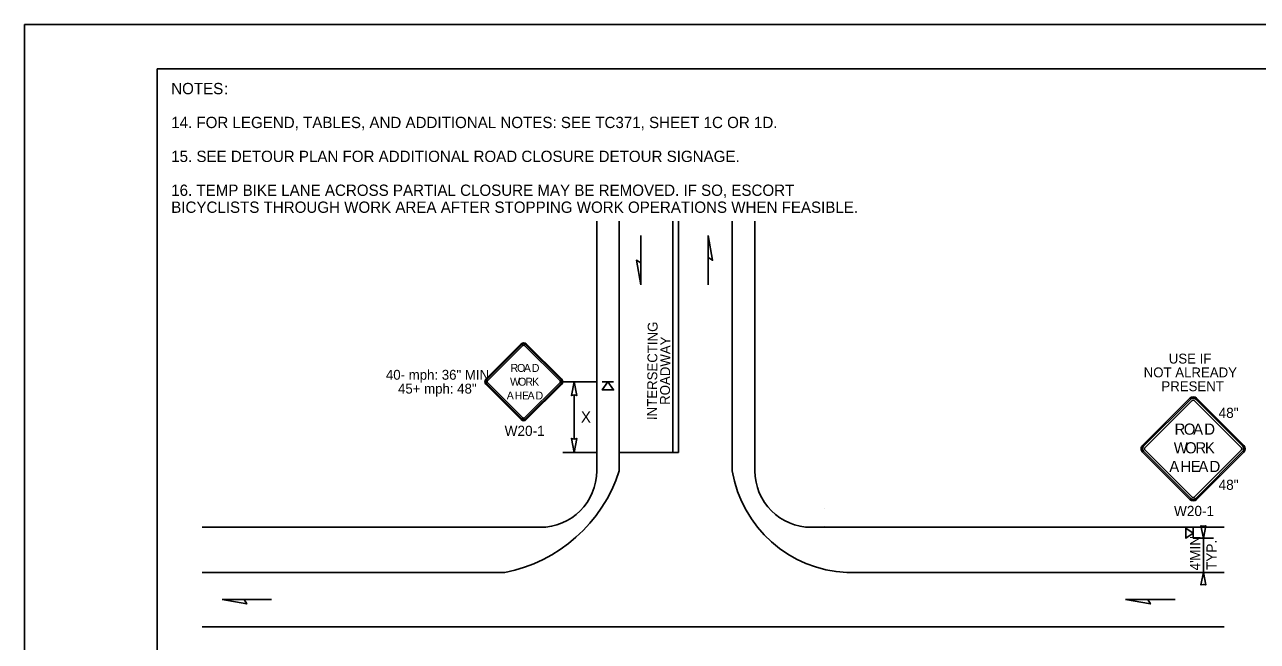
# Model space of a CAD drawing. Extents: x 99958 to 100136, y 99935 to 100013.
# Drawn here: x 100039.06 to 100047.79, y 99976.32 to 99980.69 of the extents above; entities that cross this region are included whole.
import ezdxf

# ---------------------------------------------------------------- set-up
doc = ezdxf.new("R2010")
doc.units = 0
for name, color, linetype in [('RD_ED_ShoulderPavedEdge', 7, 'Continuous'), ('RD_MK_LineDblYellowCenter', 7, 'Continuous'), ('RD_MK_LineEdgeWhite', 7, 'Continuous'), ('RD_MK_LineEdgeYellow', 7, 'Continuous'), ('RD_MK_LineLane', 7, 'Continuous'), ('RD_MK_LineStop', 7, 'Continuous'), ('SH_DE_DetailBody1Text', 7, 'Continuous'), ('SH_GI_GeneralNotesBodyText', 7, 'Continuous'), ('SH_GI_PlotLimits', 7, 'Continuous'), ('SH_GI_SheetBorder', 7, 'Continuous'), ('TR_SN_ConstructionSigns', 7, 'Continuous'), ('TR_WZ_PortableSignMountBlk-Org', 7, 'Continuous'), ('TR_WZ_WorkZoneDetails', 7, 'Continuous'), ('TR_WZ_WorkZoneTextCurrent', 7, 'Continuous')]:
    doc.layers.add(name, color=color, linetype=linetype)

msp = doc.modelspace()

# ---------------------------------------------------------------- linework, layer by layer
at = {"layer": 'RD_ED_ShoulderPavedEdge'}
for p, q in [((100040.32, 99977.1284), (100042.7119, 99977.1284)), ((100044.6319, 99977.1284), (100047.555, 99977.1284))]:
    msp.add_line(p, q, dxfattribs=at)
for points in [[(100043.1119, 99979.295), (100043.1119, 99977.5284)], [(100044.2319, 99979.295), (100044.2319, 99977.5284)]]:
    msp.add_lwpolyline(points, dxfattribs=at)
for centre, start, end in [((100042.7119, 99977.5284), 270, 0), ((100044.6319, 99977.5284), 180, 270)]:
    msp.add_arc(centre, 0.4, start, end, dxfattribs=at)
at = {"layer": 'RD_MK_LineDblYellowCenter'}
for p, q in [((100043.6519, 99979.295), (100043.6519, 99977.6584)), ((100043.6919, 99979.295), (100043.6919, 99977.6584))]:
    msp.add_line(p, q, dxfattribs=at)
at = {"layer": 'RD_MK_LineEdgeWhite'}
for p, q in [((100043.2719, 99977.5284), (100043.2719, 99979.295)), ((100044.0719, 99977.5284), (100044.0719, 99979.295))]:
    msp.add_line(p, q, dxfattribs=at)
for centre, radius, start, end in [((100042.257, 99977.8547), 1.0661, 281.08423, 342.18285), ((100044.9219, 99977.669), 0.8615, 189.3884, 267.34452)]:
    msp.add_arc(centre, radius, start, end, dxfattribs=at)
at = {"layer": 'RD_MK_LineEdgeYellow'}
for p, q in [((100040.32, 99976.8084), (100042.4619, 99976.8084)), ((100044.8819, 99976.8084), (100047.555, 99976.8084))]:
    msp.add_line(p, q, dxfattribs=at)
at = {"layer": 'RD_MK_LineLane'}
msp.add_lwpolyline([(100047.555, 99976.4244), (100040.32, 99976.4244)], dxfattribs=at)
at = {"layer": 'RD_MK_LineStop'}
msp.add_line((100043.6919, 99977.6584), (100043.2719, 99977.6584), dxfattribs=at)
at = {"layer": 'SH_GI_PlotLimits'}
msp.add_lwpolyline([(100039.0625, 99969.6875), (100056.0625, 99969.6875), (100056.0625, 99980.6875), (100039.0625, 99980.6875)], close=True, dxfattribs=at)
at = {"layer": 'SH_GI_SheetBorder'}
for q in [(100040, 99970), (100055.75, 99980.375)]:
    msp.add_line((100040, 99980.375), q, dxfattribs=at)
at = {"layer": 'TR_SN_ConstructionSigns'}
for p, q in [((100042.5782, 99978.4278), (100042.3276, 99978.1772)), ((100042.5831, 99978.4228), (100042.3325, 99978.1722)), ((100042.3395, 99978.1653), (100042.5901, 99978.4158)), ((100042.602, 99978.4158), (100042.8526, 99978.1653)), ((100042.8596, 99978.1722), (100042.609, 99978.4228)), ((100042.8645, 99978.1772), (100042.6139, 99978.4278)), ((100042.3276, 99978.1414), (100042.5782, 99977.8908)), ((100042.3325, 99978.1464), (100042.5831, 99977.8958)), ((100042.5901, 99977.9028), (100042.3395, 99978.1533)), ((100042.8526, 99978.1533), (100042.602, 99977.9028)), ((100042.609, 99977.8958), (100042.8596, 99978.1464)), ((100042.6139, 99977.8908), (100042.8645, 99978.1414)), ((100047.3109, 99978.0423), (100046.9768, 99977.7082)), ((100047.3169, 99978.0363), (100046.9828, 99977.7022)), ((100046.9927, 99977.6923), (100047.3268, 99978.0264)), ((100047.3427, 99978.0264), (100047.6768, 99977.6923)), ((100047.6868, 99977.7022), (100047.3527, 99978.0363)), ((100047.6928, 99977.7082), (100047.3586, 99978.0423)), ((100046.9768, 99977.6604), (100047.3109, 99977.3263)), ((100046.9828, 99977.6664), (100047.3169, 99977.3323)), ((100047.3268, 99977.3422), (100046.9927, 99977.6764)), ((100047.6768, 99977.6764), (100047.3427, 99977.3422)), ((100047.3527, 99977.3323), (100047.6868, 99977.6664)), ((100047.3586, 99977.3263), (100047.6928, 99977.6604))]:
    msp.add_line(p, q, dxfattribs=at)
for centre, radius, start, end in [((100042.596, 99978.4099), 0.0253, 45, 135), ((100042.596, 99978.4099), 0.0183, 45, 135), ((100042.596, 99978.4099), 0.00844, 45, 135), ((100042.3455, 99978.1593), 0.0253, 135, 225.00001), ((100042.3455, 99978.1593), 0.0183, 135, 225.00001), ((100042.3455, 99978.1593), 0.00844, 135, 225.00001), ((100042.8466, 99978.1593), 0.00844, 315.00002, 45), ((100042.8466, 99978.1593), 0.0183, 315.00002, 45), ((100042.8466, 99978.1593), 0.0253, 315.00001, 45.00001), ((100047.3348, 99978.0184), 0.0338, 45, 135), ((100047.3348, 99978.0184), 0.0253, 45, 135), ((100047.3348, 99978.0184), 0.0113, 45, 135), ((100042.596, 99977.9087), 0.0253, 225.00001, 315.00001), ((100042.596, 99977.9087), 0.0183, 225.00001, 315.00002), ((100042.596, 99977.9087), 0.00844, 225.00001, 315.00002), ((100047.0007, 99977.6843), 0.0338, 135, 225.00001), ((100047.0007, 99977.6843), 0.0253, 135, 225.00001), ((100047.6689, 99977.6843), 0.0253, 315.00002, 45), ((100047.6689, 99977.6843), 0.0338, 315.00001, 45.00001), ((100047.0007, 99977.6843), 0.0113, 135, 225.00001), ((100047.6689, 99977.6843), 0.0113, 315.00002, 45), ((100047.3348, 99977.3502), 0.0338, 225.00001, 315.00001), ((100047.3348, 99977.3502), 0.0253, 225.00001, 315.00002), ((100047.3348, 99977.3502), 0.0113, 225.00001, 315.00002)]:
    msp.add_arc(centre, radius, start, end, dxfattribs=at)
at = {"layer": 'TR_WZ_PortableSignMountBlk-Org'}
for p, q in [((100043.1519, 99978.1593), (100043.2319, 99978.1593)), ((100047.3348, 99977.1234), (100047.3348, 99977.0514))]:
    msp.add_line(p, q, dxfattribs=at)
for points in [[(100043.1919, 99978.1593), (100043.2319, 99978.1018), (100043.1519, 99978.1018)], [(100047.3348, 99977.0874), (100047.2831, 99977.0514), (100047.2831, 99977.1234)]]:
    msp.add_lwpolyline(points, close=True, dxfattribs=at)
at = {"layer": 'TR_WZ_WorkZoneDetails'}
for p, q in [((100043.4242, 99979.0021), (100043.4242, 99979.195)), ((100043.9015, 99979.0378), (100043.9015, 99978.8449)), ((100043.1119, 99978.1593), (100042.8719, 99978.1593)), ((100042.9519, 99978.0656), (100042.9519, 99977.753)), ((100043.1119, 99977.6593), (100042.8719, 99977.6593)), ((100044.7227, 99977.2606), (100044.7227, 99977.2606)), ((100044.7227, 99977.1363), (100044.7227, 99977.1363)), ((100047.3348, 99977.0514), (100047.4788, 99977.0514)), ((100047.4068, 99977.0514), (100047.4068, 99976.8084)), ((100047.3348, 99976.8084), (100047.4788, 99976.8084)), ((100040.6169, 99976.6164), (100040.8098, 99976.6164)), ((100047.0136, 99976.6164), (100047.2065, 99976.6164))]:
    msp.add_line(p, q, dxfattribs=at)
for points in [[(100043.9015, 99979.195), (100043.9323, 99979.0199), (100043.9015, 99979.0378)], [(100043.4242, 99978.8449), (100043.3933, 99979.0199), (100043.4242, 99979.0021)], [(100042.9519, 99978.1593), (100042.9712, 99978.061), (100042.9519, 99978.0656), (100042.9327, 99978.061)], [(100042.9519, 99977.6593), (100042.9712, 99977.7576), (100042.9519, 99977.753), (100042.9327, 99977.7576)], [(100047.4068, 99977.0514), (100047.3894, 99977.1398), (100047.4068, 99977.1357), (100047.4241, 99977.1398)], [(100047.4068, 99976.8084), (100047.3894, 99976.72), (100047.4068, 99976.7241), (100047.4241, 99976.72)], [(100040.4597, 99976.6164), (100040.6347, 99976.5856), (100040.6169, 99976.6164)], [(100046.8563, 99976.6164), (100047.0314, 99976.5856), (100047.0136, 99976.6164)]]:
    msp.add_lwpolyline(points, close=True, dxfattribs=at)

# ---------------------------------------------------------------- texts
at = {"layer": 'SH_DE_DetailBody1Text'}
for s, p in [('INTERSECTING', (100043.5379, 99977.8877)), ('ROADWAY', (100043.6299, 99977.9952))]:
    msp.add_text(s, height=0.07, rotation=89.5374, dxfattribs=at).set_placement(p)
at = {"layer": 'SH_GI_GeneralNotesBodyText'}
for s, p in [('NOTES', (100040.1, 99980.195)), (':', (100040.4743, 99980.195)), ('14. FOR LEGEND, TABLES, AND ADDITIONAL NOTES: SEE TC371, SHEET 1C OR 1D.', (100040.1, 99979.955)), ('15. SEE DETOUR PLAN FOR ADDITIONAL ROAD CLOSURE DETOUR SIGNAGE.', (100040.1, 99979.715)), ('16. TEMP BIKE LANE ACROSS PARTIAL CLOSURE MAY BE REMOVED. IF SO, ESCORT ', (100040.1, 99979.475)), ('BICYCLISTS THROUGH WORK AREA AFTER STOPPING WORK OPERATIONS WHEN FEASIBLE.', (100040.1, 99979.355))]:
    msp.add_text(s, height=0.08, rotation=360, dxfattribs=at).set_placement(p)
at = {"layer": 'TR_SN_ConstructionSigns'}
for s, height, p in [('R', 0.0562, (100042.5015, 99978.2288)), ('O', 0.0562, (100042.5484, 99978.2288)), ('A', 0.0562, (100042.5959, 99978.2288)), ('D', 0.0562, (100042.6524, 99978.2288)), ('W', 0.0562, (100042.4986, 99978.1312)), ('O', 0.0562, (100042.5555, 99978.1312)), ('R', 0.0562, (100042.607, 99978.1312)), ('K', 0.0562, (100042.6542, 99978.1312)), ('A', 0.0562, (100042.4751, 99978.0335)), ('H', 0.0562, (100042.5314, 99978.0335)), ('E', 0.0562, (100042.5831, 99978.0335)), ('A', 0.0562, (100042.6225, 99978.0335)), ('D', 0.0562, (100042.6787, 99978.0335)), ('R', 0.0788, (100047.2029, 99977.7842)), ('O', 0.0788, (100047.2682, 99977.7842)), ('A', 0.0788, (100047.3344, 99977.7842)), ('D', 0.0788, (100047.4131, 99977.7842)), ('W', 0.0788, (100047.197, 99977.652)), ('O', 0.0788, (100047.2773, 99977.652)), ('R', 0.0788, (100047.3505, 99977.652)), ('K', 0.0788, (100047.4175, 99977.652)), ('A', 0.0788, (100047.1655, 99977.5198)), ('H', 0.0788, (100047.2442, 99977.5198)), ('E', 0.0788, (100047.3167, 99977.5198)), ('A', 0.0788, (100047.3718, 99977.5198)), ('D', 0.0788, (100047.4505, 99977.5198))]:
    msp.add_text(s, height=height, dxfattribs=at).set_placement(p)
for s, p in [('48"', (100047.5146, 99977.9029)), ('W20-1', (100042.4602, 99977.7754)), ('48"', (100047.5146, 99977.3937)), ('W20-1', (100047.1989, 99977.2084))]:
    msp.add_text(s, height=0.072, rotation=360, dxfattribs=at).set_placement(p)
at = {"layer": 'TR_WZ_WorkZoneDetails'}
for s, p in [('USE IF', (100047.1618, 99978.2882)), ('40- mph: 36" MIN', (100041.62, 99978.1733)), ('NOT ALREADY', (100046.9842, 99978.1902)), ('45+ mph: 48"', (100041.7056, 99978.0753)), ('PRESENT', (100047.1096, 99978.0922))]:
    msp.add_text(s, height=0.07, dxfattribs=at).set_placement(p)
at = {"layer": 'TR_WZ_WorkZoneTextCurrent'}
msp.add_text('X', height=0.08, dxfattribs=at).set_placement((100043.0002, 99977.8693))
for s, p in [('MIN', (100047.3852, 99976.8916)), ('TYP.', (100047.5004, 99976.8261)), ("4'", (100047.3852, 99976.8228))]:
    msp.add_text(s, height=0.072, rotation=90, dxfattribs=at).set_placement(p)

doc.saveas('drawing.dxf')
